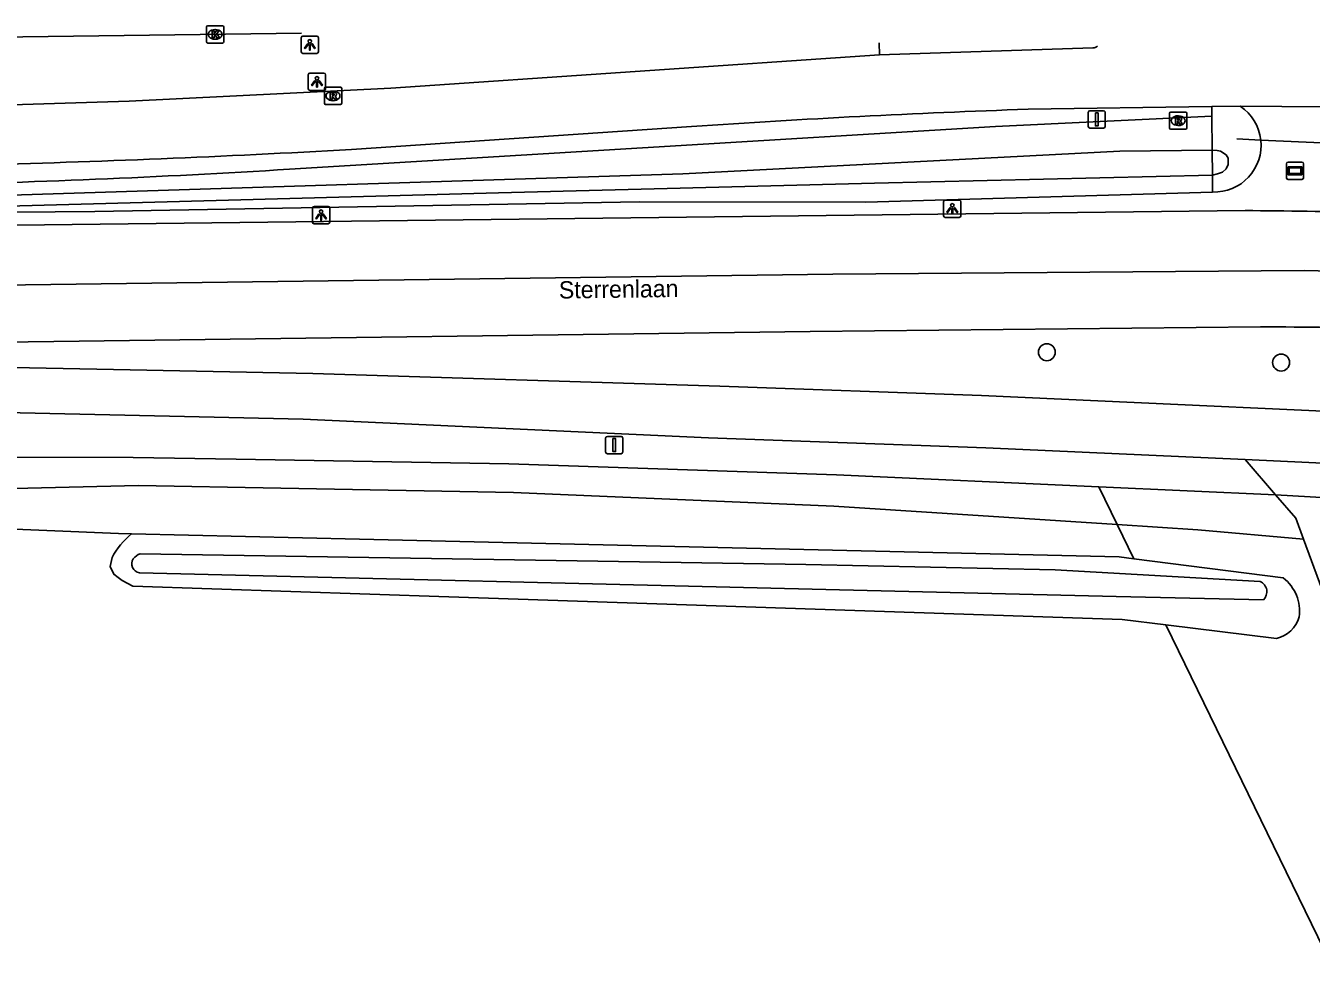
# Model space of a CAD drawing. Extents: x 162791 to 163827, y 385795 to 386523.
# Drawn here: x 163337.5 to 163411.8, y 386468.3 to 386522.6 of the extents above; entities that cross this region are included whole.
import ezdxf

# ---------------------------------------------------------------- set-up
doc = ezdxf.new("R2010")
doc.units = 0
for name, color, linetype in [('IMGEO_Berm_groen', 7, 'Continuous'), ('IMGEO_Boom', 7, 'Continuous'), ('IMGEO_Duiker', 7, 'Continuous'), ('IMGEO_Fietspad_gesloten', 7, 'Continuous'), ('IMGEO_Groenvoorziening', 7, 'Continuous'), ('IMGEO_Hek', 7, 'Continuous'), ('IMGEO_Kolk', 7, 'Continuous'), ('IMGEO_Lichtpunt', 7, 'Continuous'), ('IMGEO_Loofbos', 7, 'Continuous'), ('IMGEO_Openbare_ruimte_label', 7, 'Continuous'), ('IMGEO_OVBaan_gesloten', 7, 'Continuous'), ('IMGEO_Reclamebord', 7, 'Continuous'), ('IMGEO_Rijbaan_regionaal_gesloten', 7, 'Continuous'), ('IMGEO_Rioolput', 7, 'Continuous'), ('IMGEO_Verkeersbordpaal', 7, 'Continuous'), ('IMGEO_Verkeerseiland_gesloten', 7, 'Continuous'), ('IMGEO_Waterloop', 7, 'Continuous')]:
    doc.layers.add(name, color=color, linetype=linetype)

msp = doc.modelspace()

# ---------------------------------------------------------------- linework, layer by layer
at = {"layer": 'IMGEO_Berm_groen'}
for points in [[(163406.048, 386517.363), (163393.536, 386516.774), (163352.723, 386514.303)], [(163306.981, 386511.551), (163327.669, 386511.736), (163341.46, 386511.859), (163372.937, 386512.412), (163386.044, 386512.404), (163406.086, 386512.983)]]:
    msp.add_lwpolyline(points, dxfattribs=at)
msp.add_arc((163317.575, 387084.807), 571.586, 271.27125, 273.52546, dxfattribs=at)
at = {"layer": 'IMGEO_Boom'}
for centre in [(163396.5, 386503.718), (163410.045, 386503.118)]:
    msp.add_circle(centre, 0.489, dxfattribs=at)
at = {"layer": 'IMGEO_Duiker'}
msp.add_lwpolyline([(163407.484, 386516.051), (163408.871, 386515.991), (163412.81, 386515.819), (163421.369, 386515.254), (163422.253, 386515.196)], dxfattribs=at)
at = {"layer": 'IMGEO_Fietspad_gesloten'}
for points in [[(163447.684, 386498.2), (163437.07, 386498.936), (163422.157, 386499.862), (163392.717, 386501.21), (163377.597, 386501.753), (163354.063, 386502.487), (163341.58, 386502.733), (163336.698, 386502.829), (163322.556, 386503.048), (163312.779, 386502.838)], [(163407.967, 386497.506), (163392.983, 386498.182), (163376.942, 386498.76), (163353.5, 386499.838), (163345.782, 386500.013), (163336.276, 386500.228), (163285.095, 386499.165), (163274.146, 386499.134)], [(163407.967, 386497.506), (163416.565, 386497.119)]]:
    msp.add_lwpolyline(points, dxfattribs=at)
at = {"layer": 'IMGEO_Groenvoorziening'}
for points in [[(163282.042, 386498.022), (163308.809, 386497.509), (163318.366, 386497.664), (163343.676, 386497.629), (163349.624, 386497.527), (163365.389, 386497.256), (163384.342, 386496.626), (163399.5, 386495.937)], [(163409.721, 386495.473), (163407.967, 386497.506)], [(163400.563, 386493.754), (163384.182, 386494.806), (163365.669, 386495.597), (163352.211, 386495.853), (163343.996, 386496.009), (163308.768, 386495.17), (163287.556, 386495.542)], [(163399.5, 386495.937), (163409.721, 386495.473)], [(163399.5, 386495.937), (163400.563, 386493.754)], [(163416.729, 386495.064), (163409.721, 386495.473)], [(163409.721, 386495.473), (163410.887, 386494.12), (163411.34, 386492.903)], [(163411.34, 386492.903), (163405.235, 386493.454), (163400.563, 386493.754)], [(163400.563, 386493.754), (163401.529, 386491.768)], [(163401.529, 386491.768), (163400.676, 386491.877), (163356.77, 386492.902), (163343.577, 386493.21)], [(163414.652, 386483.994), (163413.65, 386486.689), (163412.272, 386490.396), (163411.34, 386492.903)], [(163401.529, 386491.768), (163410.163, 386490.665)], [(163409.774, 386487.164), (163403.388, 386487.947)]]:
    msp.add_lwpolyline(points, dxfattribs=at)
for centre, radius, start, end in [((163408.719, 386488.761), 2.389, 351.47211, 52.82028), ((163409.392, 386488.876), 1.754, 282.59034, 344.49047)]:
    msp.add_arc(centre, radius, start, end, dxfattribs=at)
at = {"layer": 'IMGEO_Hek'}
msp.add_lwpolyline([(163287.556, 386495.542), (163342.835, 386493.227)], dxfattribs=at)
at = {"layer": 'IMGEO_Kolk'}
for p, q in [((163347.917, 386521.677), (163347.917, 386522.529)), ((163347.992, 386522.603), (163348.844, 386522.603)), ((163348.405, 386522.383), (163348.43, 386522.383)), ((163348.918, 386522.529), (163348.918, 386521.677)), ((163348.844, 386521.603), (163347.992, 386521.603)), ((163348.428, 386521.823), (163348.403, 386521.823))]:
    msp.add_line(p, q, dxfattribs=at)
for points in [[(163347.917, 386521.677), (163347.917, 386522.529)], [(163347.992, 386522.603), (163348.844, 386522.603)], [(163348.238, 386522.303), (163348.361, 386522.303), (163348.361, 386522.152), (163348.491, 386522.303), (163348.655, 386522.303), (163348.509, 386522.152), (163348.662, 386521.903), (163348.51, 386521.903), (163348.425, 386522.067), (163348.361, 386522), (163348.361, 386521.903), (163348.238, 386521.903), (163348.238, 386522.303)], [(163348.918, 386522.529), (163348.918, 386521.677)], [(163348.844, 386521.603), (163347.992, 386521.603)]]:
    msp.add_lwpolyline(points, dxfattribs=at)
for centre, start, end in [((163347.994, 386522.527), 91.55205, 178.44795), ((163347.994, 386522.527), 91.55205, 178.44795), ((163348.842, 386522.527), 1.55205, 88.44795), ((163348.842, 386522.527), 1.55205, 88.44795), ((163347.994, 386521.679), 181.55205, 268.44795), ((163347.994, 386521.679), 181.55205, 268.44795), ((163348.842, 386521.679), 271.55205, 358.44795), ((163348.842, 386521.679), 271.55205, 358.44795)]:
    msp.add_arc(centre, 0.0765, start, end, dxfattribs=at)
for centre, major_axis, ratio, start_param, end_param in [((163348.404, 386522.103), (-0.387, 0.002), 0.722429, 4.712389, 7.853982), ((163348.429, 386522.103), (-0.39, 0.002), 0.717154, 1.570796, 4.712389)]:
    msp.add_ellipse(centre, major_axis=major_axis, ratio=ratio, start_param=start_param, end_param=end_param, dxfattribs=at)
at = {"layer": 'IMGEO_Lichtpunt'}
for p, q in [((163353.395, 386521.904), (163353.395, 386521.097)), ((163353.395, 386521.904), (163353.395, 386521.097)), ((163354.297, 386521.999), (163353.489, 386521.999)), ((163354.297, 386521.999), (163353.489, 386521.999)), ((163354.391, 386521.097), (163354.391, 386521.904)), ((163354.391, 386521.097), (163354.391, 386521.904)), ((163353.489, 386521.003), (163354.297, 386521.003)), ((163353.489, 386521.003), (163354.297, 386521.003)), ((163353.805, 386519.764), (163353.805, 386518.957)), ((163353.805, 386519.764), (163353.805, 386518.957)), ((163354.707, 386519.859), (163353.899, 386519.859)), ((163354.707, 386519.859), (163353.899, 386519.859)), ((163354.801, 386518.957), (163354.801, 386519.764)), ((163354.801, 386518.957), (163354.801, 386519.764)), ((163353.899, 386518.863), (163354.707, 386518.863)), ((163353.899, 386518.863), (163354.707, 386518.863)), ((163354.045, 386512.053), (163354.045, 386511.246)), ((163354.045, 386512.053), (163354.045, 386511.246)), ((163354.947, 386512.148), (163354.139, 386512.148)), ((163354.947, 386512.148), (163354.139, 386512.148)), ((163355.041, 386511.246), (163355.041, 386512.053)), ((163355.041, 386511.246), (163355.041, 386512.053)), ((163390.535, 386512.42), (163390.535, 386511.613)), ((163390.535, 386512.42), (163390.535, 386511.613)), ((163391.437, 386512.515), (163390.629, 386512.515)), ((163391.437, 386512.515), (163390.629, 386512.515)), ((163391.531, 386511.613), (163391.531, 386512.42)), ((163391.531, 386511.613), (163391.531, 386512.42)), ((163354.139, 386511.152), (163354.947, 386511.152)), ((163354.139, 386511.152), (163354.947, 386511.152)), ((163390.629, 386511.519), (163391.437, 386511.519)), ((163390.629, 386511.519), (163391.437, 386511.519))]:
    msp.add_line(p, q, dxfattribs=at)
for points in [[(163353.769, 386521.568), (163353.808, 386521.54), (163353.62, 386521.278), (163353.582, 386521.305), (163353.769, 386521.568)], [(163353.981, 386521.54), (163354.019, 386521.567), (163354.206, 386521.305), (163354.167, 386521.277), (163353.981, 386521.54)], [(163353.871, 386521.52), (163353.918, 386521.52), (163353.918, 386521.198), (163353.871, 386521.198), (163353.871, 386521.52)], [(163354.179, 386519.428), (163354.218, 386519.4), (163354.03, 386519.138), (163353.992, 386519.165), (163354.179, 386519.428)], [(163354.281, 386519.38), (163354.328, 386519.38), (163354.328, 386519.058), (163354.281, 386519.058), (163354.281, 386519.38)], [(163354.391, 386519.4), (163354.429, 386519.427), (163354.616, 386519.165), (163354.577, 386519.137), (163354.391, 386519.4)], [(163390.909, 386512.084), (163390.948, 386512.056), (163390.76, 386511.794), (163390.722, 386511.821), (163390.909, 386512.084)], [(163391.011, 386512.036), (163391.058, 386512.036), (163391.058, 386511.714), (163391.011, 386511.714), (163391.011, 386512.036)], [(163391.121, 386512.056), (163391.159, 386512.083), (163391.346, 386511.821), (163391.307, 386511.793), (163391.121, 386512.056)], [(163354.419, 386511.717), (163354.458, 386511.689), (163354.27, 386511.427), (163354.232, 386511.454), (163354.419, 386511.717)], [(163354.521, 386511.669), (163354.568, 386511.669), (163354.568, 386511.347), (163354.521, 386511.347), (163354.521, 386511.669)], [(163354.631, 386511.689), (163354.669, 386511.716), (163354.856, 386511.454), (163354.817, 386511.426), (163354.631, 386511.689)]]:
    msp.add_lwpolyline(points, dxfattribs=at)
for centre in [(163353.894, 386521.702), (163354.304, 386519.562), (163354.544, 386511.851), (163391.034, 386512.218)]:
    msp.add_circle(centre, 0.0994, dxfattribs=at)
for centre, start, end in [((163353.489, 386521.904), 90, 180), ((163353.489, 386521.904), 90, 180), ((163354.297, 386521.904), 0, 90), ((163354.297, 386521.904), 0, 90), ((163353.489, 386521.097), 180, 270), ((163353.489, 386521.097), 180, 270), ((163354.297, 386521.097), 270, 0), ((163354.297, 386521.097), 270, 360), ((163353.899, 386519.764), 90, 180), ((163353.899, 386519.764), 90, 180), ((163354.707, 386519.764), 0, 90), ((163354.707, 386519.764), 0, 90), ((163353.899, 386518.957), 180, 270), ((163353.899, 386518.957), 180, 270), ((163354.707, 386518.957), 270, 0), ((163354.707, 386518.957), 270, 360), ((163354.139, 386512.053), 90, 180), ((163354.139, 386512.053), 90, 180), ((163354.947, 386512.053), 0, 90), ((163354.947, 386512.053), 0, 90), ((163390.629, 386512.42), 90, 180), ((163390.629, 386512.42), 90, 180), ((163391.437, 386512.42), 0, 90), ((163391.437, 386512.42), 0, 90), ((163354.139, 386511.246), 180, 270), ((163354.139, 386511.246), 180, 270), ((163354.947, 386511.246), 270, 0), ((163354.947, 386511.246), 270, 360), ((163390.629, 386511.613), 180, 270), ((163390.629, 386511.613), 180, 270), ((163391.437, 386511.613), 270, 0), ((163391.437, 386511.613), 270, 360)]:
    msp.add_arc(centre, 0.0946, start, end, dxfattribs=at)
at = {"layer": 'IMGEO_Loofbos'}
for points in [[(163343.577, 386493.21), (163342.835, 386493.227), (163287.556, 386495.542)], [(163403.388, 386487.947), (163400.855, 386488.258), (163361.92, 386489.569), (163343.653, 386490.184), (163343.048, 386490.514), (163342.818, 386490.69), (163342.57, 386490.879), (163342.345, 386491.332), (163342.457, 386491.84)], [(163442.645, 386407.261), (163421.295, 386451.142), (163403.388, 386487.947)]]:
    msp.add_lwpolyline(points, dxfattribs=at)
msp.add_arc((163346.47, 386489.702), 4.547, 129.51185, 151.9549, dxfattribs=at)
at = {"layer": 'IMGEO_OVBaan_gesloten'}
for points in [[(163407.961, 386511.911), (163328.845, 386510.975), (163320.348, 386510.874), (163278.578, 386510.168)], [(163448.04, 386506.684), (163426.029, 386508.092), (163411.373, 386508.445), (163384.122, 386508.228), (163330.158, 386507.517), (163278.133, 386506.832)], [(163408.845, 386505.184), (163382.823, 386504.918), (163339.084, 386504.348), (163313.816, 386504.019)]]:
    msp.add_lwpolyline(points, dxfattribs=at)
for centre, radius, start, end in [((163405.171, 386125.878), 386.043, 87.45061, 89.58585), ((163408.789, 386200.589), 304.595, 87.04502, 89.98942)]:
    msp.add_arc(centre, radius, start, end, dxfattribs=at)
at = {"layer": 'IMGEO_Reclamebord'}
for p, q in [((163410.351, 386513.814), (163410.351, 386514.614)), ((163410.351, 386514.614), (163410.351, 386513.814)), ((163410.451, 386514.714), (163411.241, 386514.714)), ((163411.241, 386514.714), (163410.451, 386514.714)), ((163411.341, 386514.614), (163411.341, 386513.814)), ((163411.341, 386513.814), (163411.341, 386514.614)), ((163411.241, 386513.714), (163410.451, 386513.714)), ((163410.451, 386513.714), (163411.241, 386513.714))]:
    msp.add_line(p, q, dxfattribs=at)
for points in [[(163410.452, 386514.446), (163411.24, 386514.446), (163411.24, 386513.982), (163410.452, 386513.982), (163410.452, 386514.446)], [(163410.517, 386514.381), (163410.517, 386514.047), (163411.175, 386514.047), (163411.175, 386514.381), (163410.517, 386514.381)]]:
    msp.add_lwpolyline(points, dxfattribs=at)
for centre, start, end in [((163410.451, 386514.614), 90, 180), ((163410.451, 386514.614), 90, 180), ((163411.241, 386514.614), 0, 90), ((163411.241, 386514.614), 360, 90), ((163410.451, 386513.814), 180, 270), ((163410.451, 386513.814), 180, 270), ((163411.241, 386513.814), 270, 0), ((163411.241, 386513.814), 270, 0)]:
    msp.add_arc(centre, 0.1, start, end, dxfattribs=at)
at = {"layer": 'IMGEO_Rijbaan_regionaal_gesloten'}
for points in [[(163277.927, 386521.185), (163312.376, 386521.633), (163353.405, 386522.168)], [(163386.835, 386520.916), (163358.569, 386518.995), (163343.445, 386518.239), (163328.642, 386517.781), (163318.563, 386517.629), (163307.634, 386517.464), (163307.622, 386517.691), (163307.031, 386517.639), (163307.015, 386517.467), (163289.038, 386517.264)], [(163386.835, 386520.916), (163399.159, 386521.317)], [(163395.419, 386517.772), (163406.043, 386517.934)], [(163406.043, 386517.934), (163407.685, 386517.941)], [(163407.685, 386517.941), (163417.332, 386517.881)], [(163356.293, 386515.445), (163375.96, 386516.773)]]:
    msp.add_lwpolyline(points, dxfattribs=at)
for centre, radius, start, end in [((163399.131, 386521.818), 0.502, 273.1628, 305.74883), ((163414.785, 385950.543), 567.559, 91.95537, 93.92246), ((163316.613, 387213.436), 699.118, 271.450334, 273.253694)]:
    msp.add_arc(centre, radius, start, end, dxfattribs=at)
at = {"layer": 'IMGEO_Rioolput'}
for p, q in [((163354.732, 386518.119), (163354.732, 386518.971)), ((163354.807, 386519.045), (163355.659, 386519.045)), ((163355.22, 386518.825), (163355.245, 386518.825)), ((163355.733, 386518.971), (163355.733, 386518.119)), ((163355.659, 386518.045), (163354.807, 386518.045)), ((163355.243, 386518.265), (163355.218, 386518.265)), ((163403.597, 386516.685), (163403.597, 386517.537)), ((163403.672, 386517.611), (163404.524, 386517.611)), ((163404.085, 386517.391), (163404.11, 386517.391)), ((163404.598, 386517.537), (163404.598, 386516.685)), ((163404.524, 386516.611), (163403.672, 386516.611)), ((163404.108, 386516.831), (163404.083, 386516.831))]:
    msp.add_line(p, q, dxfattribs=at)
for points in [[(163354.732, 386518.119), (163354.732, 386518.971)], [(163354.807, 386519.045), (163355.659, 386519.045)], [(163355.321, 386518.743), (163355.069, 386518.745), (163355.069, 386518.345)], [(163355.247, 386518.664), (163355.193, 386518.664), (163355.193, 386518.583)], [(163355.193, 386518.583), (163355.245, 386518.583)], [(163355.733, 386518.971), (163355.733, 386518.119)], [(163355.659, 386518.045), (163354.807, 386518.045)], [(163355.069, 386518.345), (163355.193, 386518.345), (163355.193, 386518.507), (163355.204, 386518.507)], [(163355.251, 386518.478), (163355.322, 386518.345), (163355.462, 386518.345), (163355.397, 386518.471)], [(163403.597, 386516.685), (163403.597, 386517.537)], [(163403.672, 386517.611), (163404.524, 386517.611)], [(163404.186, 386517.309), (163403.934, 386517.311), (163403.934, 386516.911)], [(163404.112, 386517.23), (163404.058, 386517.23), (163404.058, 386517.149)], [(163404.058, 386517.149), (163404.11, 386517.149)], [(163404.598, 386517.537), (163404.598, 386516.685)], [(163404.524, 386516.611), (163403.672, 386516.611)], [(163403.934, 386516.911), (163404.058, 386516.911), (163404.058, 386517.073), (163404.069, 386517.073)], [(163404.116, 386517.044), (163404.187, 386516.911), (163404.327, 386516.911), (163404.262, 386517.037)]]:
    msp.add_lwpolyline(points, dxfattribs=at)
for centre, radius, start, end in [((163354.809, 386518.969), 0.0765, 91.55205, 178.44795), ((163354.809, 386518.969), 0.0765, 91.55205, 178.44795), ((163355.229, 386518.772), 0.19, 274.7715, 282.96867), ((163355.253, 386518.568), 0.0964, 77.00612, 93.18647), ((163355.267, 386518.625), 0.0378, 276.66336, 79.67722), ((163355.32, 386518.633), 0.109, 350.36119, 89.41601), ((163355.318, 386518.633), 0.112, 277.58423, 350.98172), ((163355.657, 386518.969), 0.0765, 1.55205, 88.44795), ((163355.657, 386518.969), 0.0765, 1.55205, 88.44795), ((163354.809, 386518.121), 0.0765, 181.55205, 268.44795), ((163354.809, 386518.121), 0.0765, 181.55205, 268.44795), ((163355.203, 386518.454), 0.0533, 26.02933, 88.69889), ((163355.302, 386518.418), 0.108, 29.51342, 73.79051), ((163355.657, 386518.121), 0.0765, 271.55205, 358.44795), ((163355.657, 386518.121), 0.0765, 271.55205, 358.44795), ((163403.674, 386517.535), 0.0765, 91.55205, 178.44795), ((163403.674, 386517.535), 0.0765, 91.55205, 178.44795), ((163404.094, 386517.338), 0.19, 274.7715, 282.96867), ((163404.118, 386517.134), 0.0964, 77.00612, 93.18647), ((163404.132, 386517.191), 0.0378, 276.66336, 79.67722), ((163404.185, 386517.199), 0.109, 350.36119, 89.41601), ((163404.183, 386517.199), 0.112, 277.58423, 350.98172), ((163404.167, 386516.984), 0.108, 29.51342, 73.79051), ((163404.522, 386517.535), 0.0765, 1.55205, 88.44795), ((163404.522, 386517.535), 0.0765, 1.55205, 88.44795), ((163403.674, 386516.687), 0.0765, 181.55205, 268.44795), ((163403.674, 386516.687), 0.0765, 181.55205, 268.44795), ((163404.068, 386517.02), 0.0533, 26.02933, 88.69889), ((163404.522, 386516.687), 0.0765, 271.55205, 358.44795), ((163404.522, 386516.687), 0.0765, 271.55205, 358.44795)]:
    msp.add_arc(centre, radius, start, end, dxfattribs=at)
for centre, major_axis, ratio, start_param, end_param in [((163355.219, 386518.545), (-0.387, 0.002), 0.722429, 4.712389, 7.853982), ((163355.244, 386518.545), (-0.39, 0.002), 0.717154, 1.570796, 4.712389), ((163404.084, 386517.111), (-0.387, 0.002), 0.722429, 4.712389, 7.853982), ((163404.109, 386517.111), (-0.39, 0.002), 0.717154, 1.570796, 4.712389)]:
    msp.add_ellipse(centre, major_axis=major_axis, ratio=ratio, start_param=start_param, end_param=end_param, dxfattribs=at)
at = {"layer": 'IMGEO_Verkeersbordpaal'}
for p, q in [((163398.892, 386516.783), (163398.892, 386517.583)), ((163398.892, 386517.583), (163398.892, 386516.783)), ((163398.992, 386517.683), (163399.782, 386517.683)), ((163399.782, 386517.683), (163398.992, 386517.683)), ((163399.882, 386517.583), (163399.882, 386516.783)), ((163399.882, 386516.783), (163399.882, 386517.583)), ((163399.782, 386516.683), (163398.992, 386516.683)), ((163398.992, 386516.683), (163399.782, 386516.683)), ((163370.995, 386497.951), (163370.995, 386498.751)), ((163370.995, 386498.751), (163370.995, 386497.951)), ((163371.095, 386498.851), (163371.885, 386498.851)), ((163371.885, 386498.851), (163371.095, 386498.851)), ((163371.985, 386498.751), (163371.985, 386497.951)), ((163371.985, 386497.951), (163371.985, 386498.751)), ((163371.885, 386497.851), (163371.095, 386497.851)), ((163371.095, 386497.851), (163371.885, 386497.851))]:
    msp.add_line(p, q, dxfattribs=at)
for points in [[(163399.312, 386517.558), (163399.462, 386517.558), (163399.462, 386516.808), (163399.312, 386516.808), (163399.312, 386517.558)], [(163371.415, 386498.726), (163371.565, 386498.726), (163371.565, 386497.976), (163371.415, 386497.976), (163371.415, 386498.726)]]:
    msp.add_lwpolyline(points, dxfattribs=at)
for centre, start, end in [((163398.992, 386517.583), 90, 180), ((163398.992, 386517.583), 90, 180), ((163399.782, 386517.583), 0, 90), ((163399.782, 386517.583), 360, 90), ((163398.992, 386516.783), 180, 270), ((163398.992, 386516.783), 180, 270), ((163399.782, 386516.783), 270, 0), ((163399.782, 386516.783), 270, 0), ((163371.095, 386498.751), 90, 180), ((163371.095, 386498.751), 90, 180), ((163371.885, 386498.751), 0, 90), ((163371.885, 386498.751), 360, 90), ((163371.095, 386497.951), 180, 270), ((163371.095, 386497.951), 180, 270), ((163371.885, 386497.951), 270, 0), ((163371.885, 386497.951), 270, 0)]:
    msp.add_arc(centre, 0.1, start, end, dxfattribs=at)
at = {"layer": 'IMGEO_Verkeerseiland_gesloten'}
for points in [[(163386.815, 386521.618), (163386.835, 386520.916)], [(163406.043, 386517.934), (163406.048, 386517.363)], [(163406.065, 386515.398), (163406.048, 386517.363)], [(163406.077, 386513.965), (163406.376, 386514.035), (163406.647, 386514.14), (163406.868, 386514.325), (163406.986, 386514.577), (163406.979, 386514.934), (163406.863, 386515.128), (163406.544, 386515.34), (163406.351, 386515.384), (163406.065, 386515.398)], [(163406.086, 386512.983), (163406.077, 386513.965)]]:
    msp.add_lwpolyline(points, dxfattribs=at)
for centre, radius, start, end in [((163406.176, 386515.687), 2.712, 6.42556, 56.1908), ((163406.179, 386515.69), 2.708, 268.02422, 6.38478)]:
    msp.add_arc(centre, radius, start, end, dxfattribs=at)
at = {"layer": 'IMGEO_Waterloop'}
for points in [[(163406.077, 386513.965), (163386.544, 386513.487), (163364.791, 386512.929), (163324.333, 386511.829), (163307.737, 386511.865), (163307.619, 386511.919), (163307.501, 386512.021), (163307.469, 386512.101), (163307.472, 386512.258), (163307.511, 386512.339), (163307.596, 386512.429), (163307.699, 386512.508), (163336.621, 386512.796), (163375.455, 386514.037), (163400.711, 386515.351), (163406.065, 386515.398)], [(163406.065, 386515.398), (163406.077, 386513.965)], [(163344.085, 386492.067), (163382.561, 386491.434), (163396.982, 386491.142), (163408.832, 386490.453)], [(163409.018, 386489.394), (163400.518, 386489.6), (163383.729, 386490.005), (163344.037, 386490.964)]]:
    msp.add_lwpolyline(points, dxfattribs=at)
for centre, radius, start, end in [((163344.466, 386491.152), 0.991, 112.61237, 141.72545), ((163344.119, 386491.477), 0.519, 146.14972, 260.88398), ((163408.582, 386489.863), 0.641, 312.90063, 67.02272)]:
    msp.add_arc(centre, radius, start, end, dxfattribs=at)

# ---------------------------------------------------------------- texts
at = {"layer": 'IMGEO_Openbare_ruimte_label'}
msp.add_text('Sterrenlaan', height=1, rotation=0.7448, dxfattribs=at).set_placement((163368.296, 386506.822))

doc.saveas('drawing.dxf')
